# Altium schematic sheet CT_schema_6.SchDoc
size 371 x 336 mm
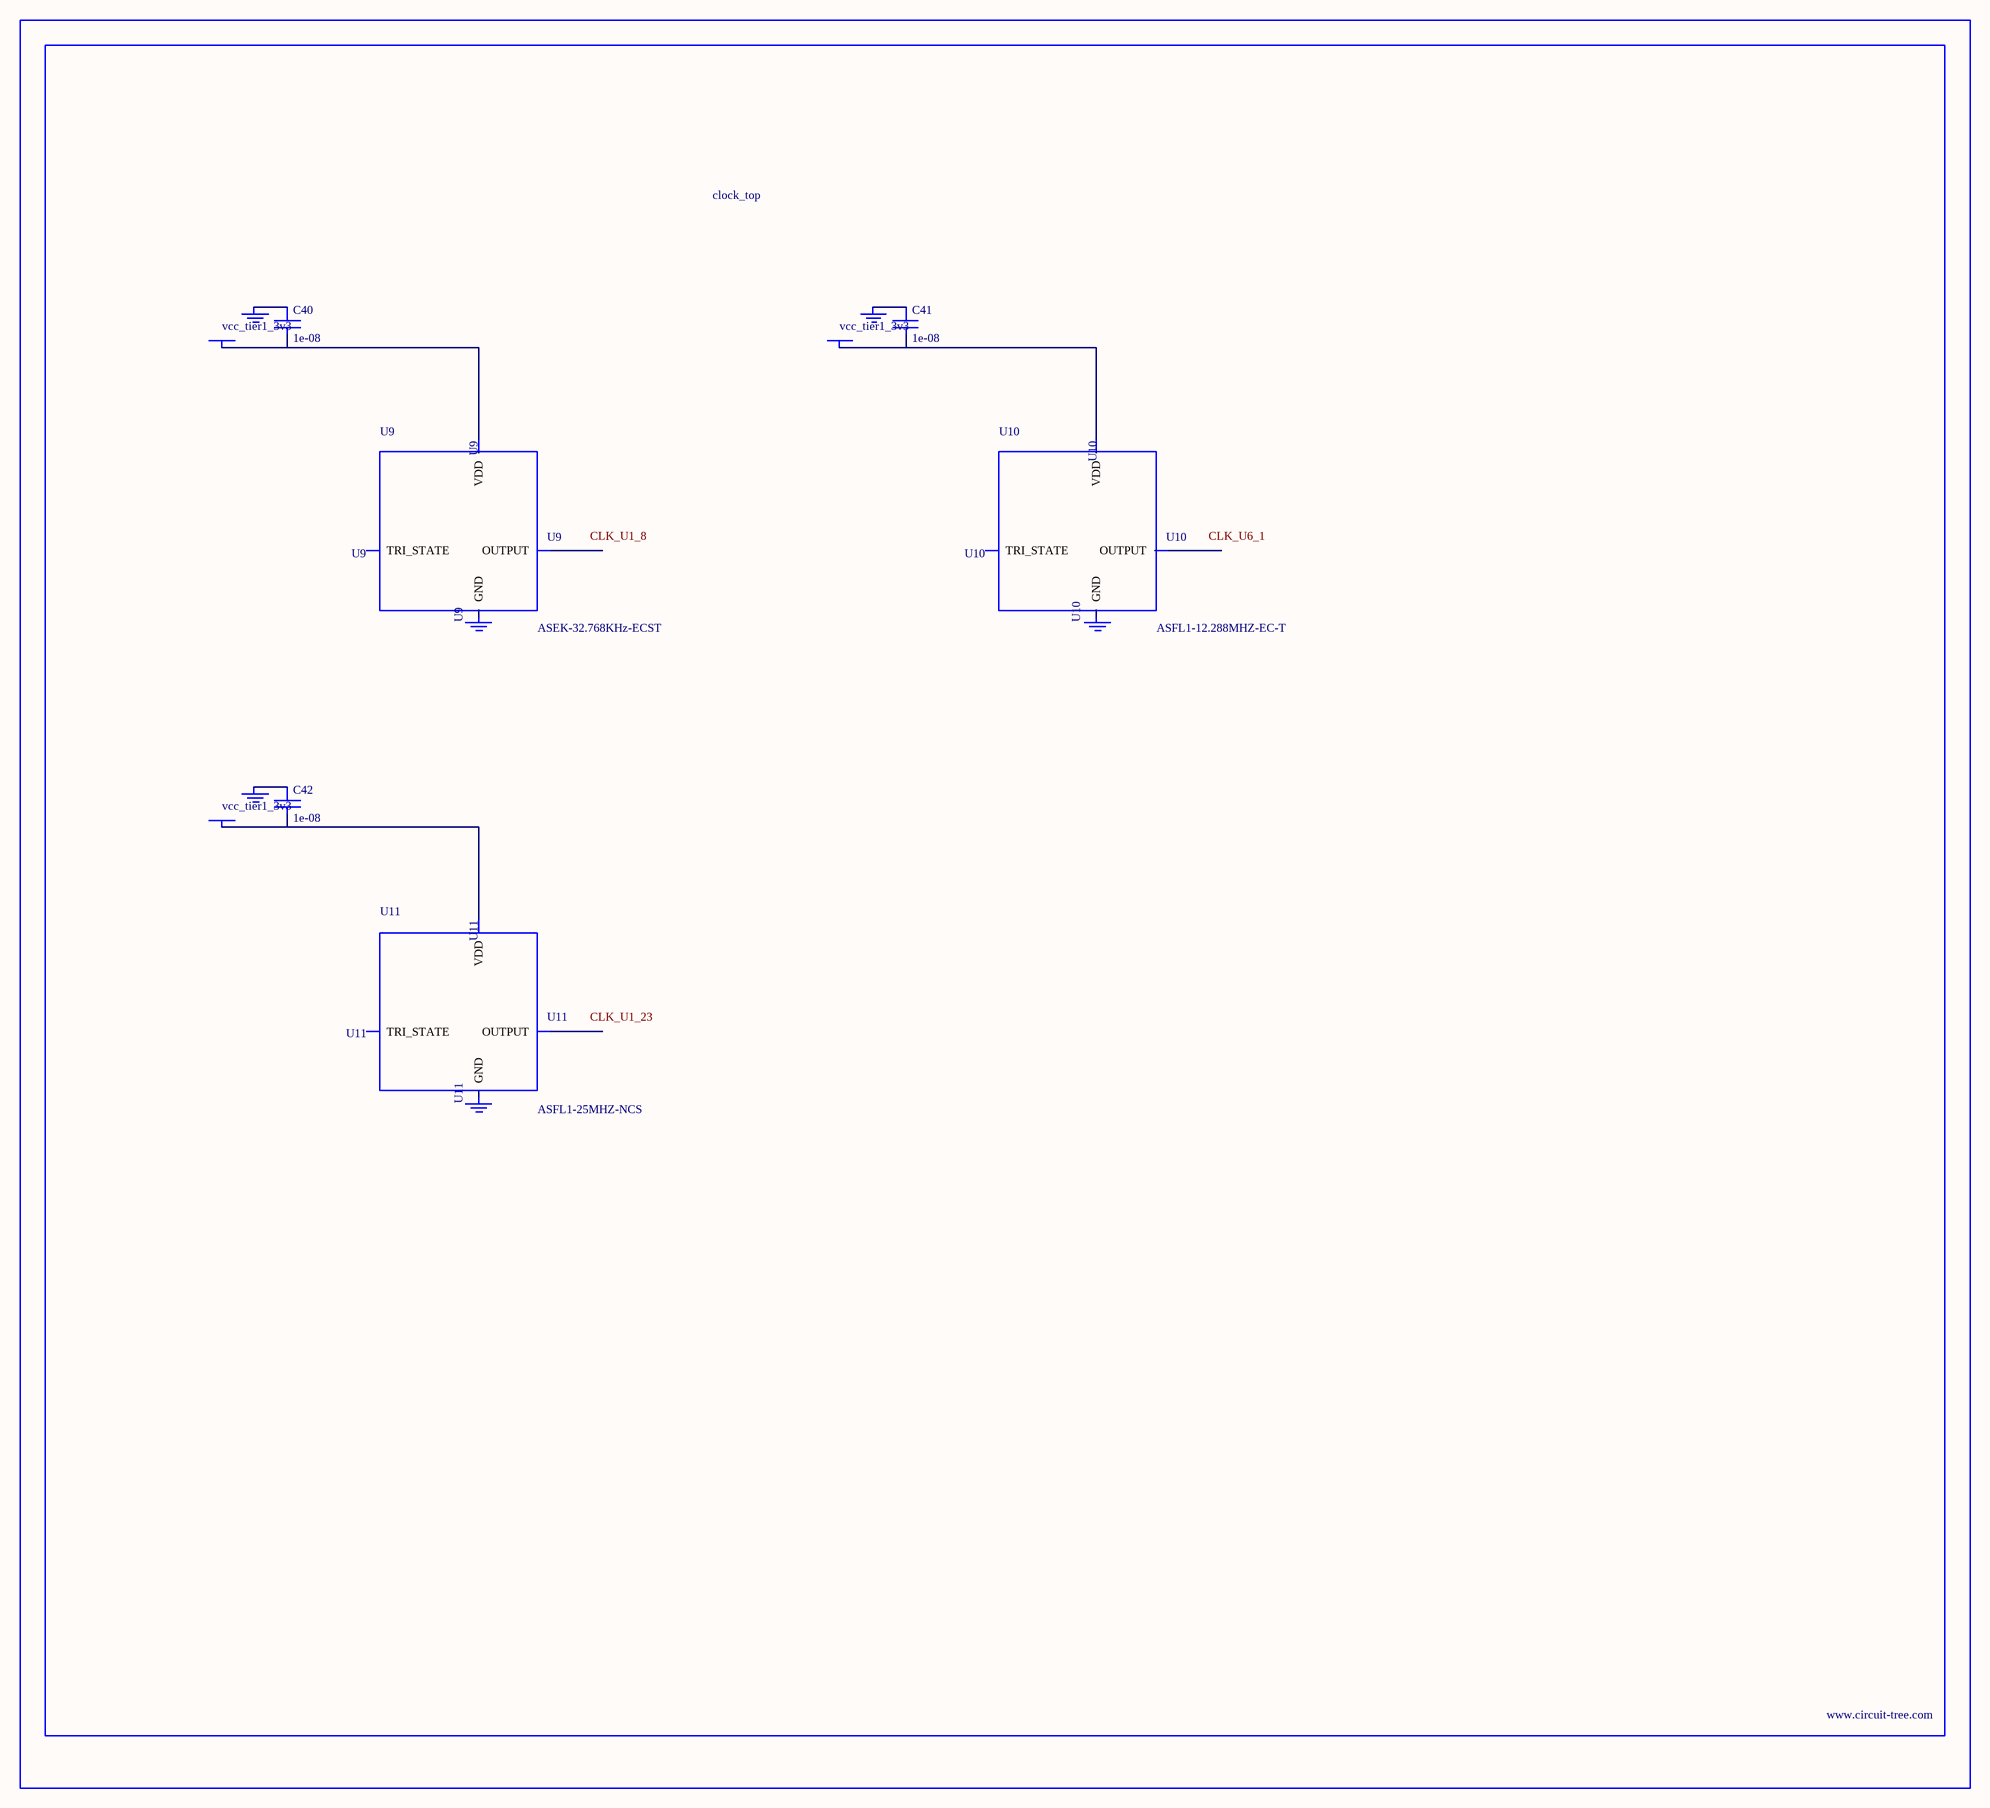
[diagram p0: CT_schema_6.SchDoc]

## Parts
BORDER5  (no value)
C40  1e-08  [C0402]
C41  1e-08  [C0402]
C42  1e-08  [C0402]
GND_INSTANCE_5_0  (no value)
GND_INSTANCE_5_1  (no value)
GND_INSTANCE_5_2  (no value)
GND_INSTANCE_5_3  (no value)
GND_INSTANCE_5_4  (no value)
GND_INSTANCE_5_5  (no value)
POWER_INSTANCE_5_0  vcc_tier1_3v3
POWER_INSTANCE_5_1  vcc_tier1_3v3
POWER_INSTANCE_5_2  vcc_tier1_3v3
U9  ASEK-32.768KHz-ECST  [ASEK]
U10  ASFL1-12.288MHZ-EC-T  [ASFL1]
U11  ASFL1-25MHZ-NCS  [ASFL1]

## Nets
NetC40_1: C40.1 GND_INSTANCE_5_0.0(GND)
NetC40_2: C40.2 POWER_INSTANCE_5_0.0(PWR) U9.4(VDD)
NetC41_1: C41.1 GND_INSTANCE_5_2.0(GND)
NetC41_2: C41.2 POWER_INSTANCE_5_1.0(PWR) U10.4(VDD)
NetC42_1: C42.1 GND_INSTANCE_5_4.0(GND)
NetC42_2: C42.2 POWER_INSTANCE_5_2.0(PWR) U11.4(VDD)

Not connected (* = marked no-connect by the designer): GND_INSTANCE_5_1 0(GND); GND_INSTANCE_5_3 0(GND); GND_INSTANCE_5_5 0(GND); U9 1(TRI_STATE) 2(GND) 3(OUTPUT); U10 1(TRI_STATE) 2(GND) 3(OUTPUT); U11 1(TRI_STATE) 2(GND) 3(OUTPUT)

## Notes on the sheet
- Labels drawn without touching a wire or pin: CLK_U1_8, CLK_U1_23, CLK_U6_1

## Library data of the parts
BORDER5 = BORDER_PAGE5
C40-C42 = C0402C103K3RAC
GND_INSTANCE_5_0-GND_INSTANCE_5_5 = GND
POWER_INSTANCE_5_0-POWER_INSTANCE_5_2 = PWR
